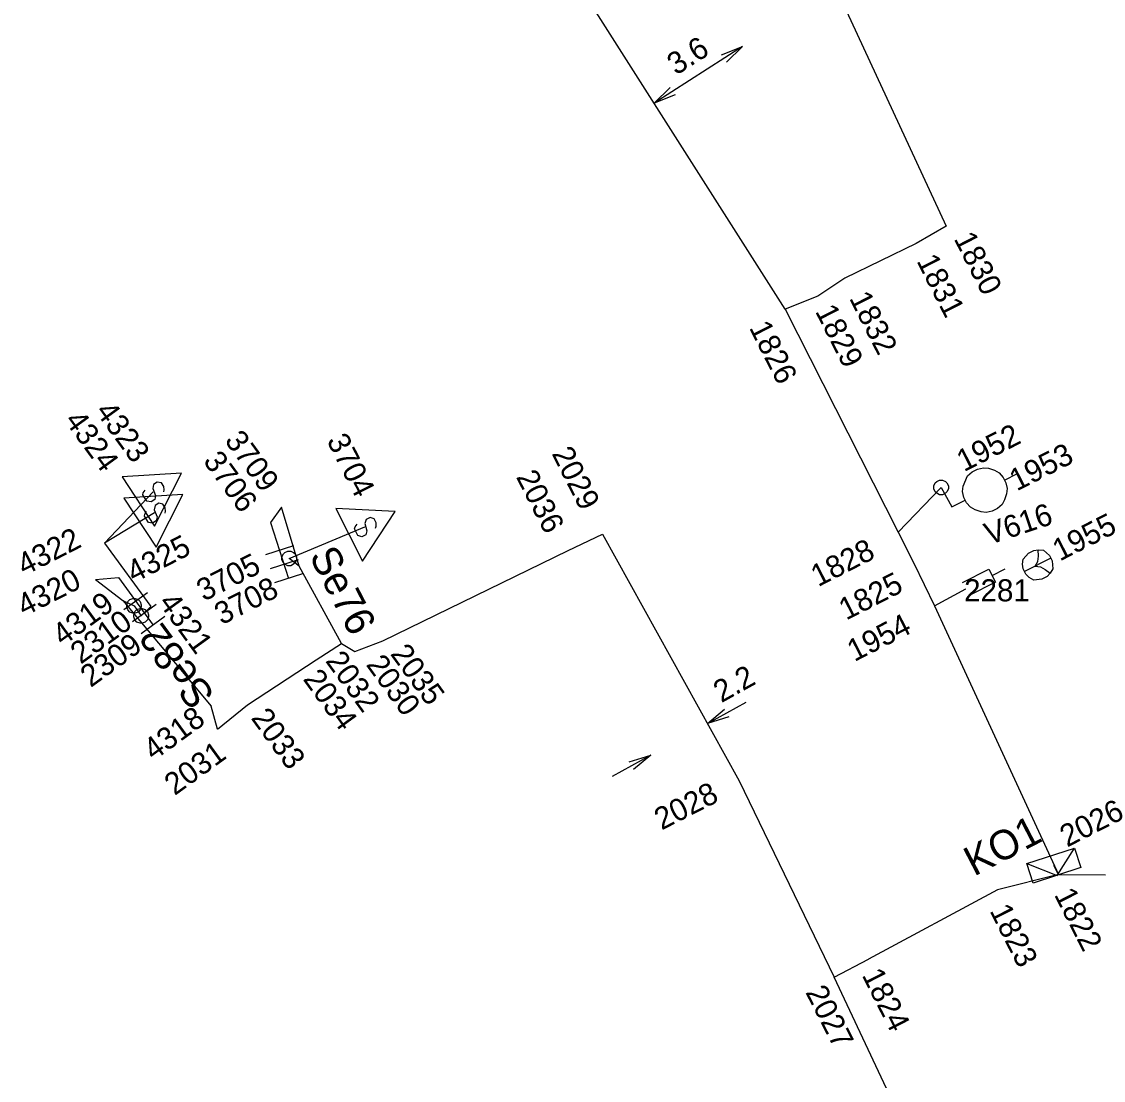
# Model space of a CAD drawing. Extents: x -535557 to -534097, y -1142175 to -1136716.
# Drawn here: x -534476.46 to -534439.74, y -1139633.14 to -1139597.2 of the extents above; entities that cross this region are included whole.
import ezdxf

# ---------------------------------------------------------------- set-up
doc = ezdxf.new("R2010")
doc.units = 0
doc.layers.add('Default', color=7, linetype='Continuous')
doc.layers.add('SS_SZDC', color=7, linetype='Continuous')

# ---------------------------------------------------------------- blocks, each defined once
blk = doc.blocks.new('POINT_DISPLAY')
at = {"layer": 'Default'}
blk.add_line((0, 0), (0, 0), dxfattribs=at)

msp = doc.modelspace()

# ---------------------------------------------------------------- linework, layer by layer
at = {"layer": 'SS_SZDC'}
for p, q in [((-534451.939, -1139589.35), (-534445.079, -1139604.139)), ((-534450.539, -1139606.959), (-534458.239, -1139594.87)), ((-534451.987, -1139598.045), (-534454.996, -1139599.962)), ((-534452.7, -1139598.322), (-534451.987, -1139598.045)), ((-534451.987, -1139598.045), (-534452.539, -1139598.575)), ((-534454.996, -1139599.962), (-534454.444, -1139599.433)), ((-534454.283, -1139599.686), (-534454.996, -1139599.962)), ((-534445.079, -1139604.139), (-534446.1, -1139604.729)), ((-534446.1, -1139604.729), (-534448.52, -1139605.909)), ((-534448.52, -1139605.909), (-534449.43, -1139606.52)), ((-534449.43, -1139606.52), (-534450.539, -1139606.959)), ((-534450.539, -1139606.959), (-534446.71, -1139614.53)), ((-534471.038, -1139612.528), (-534473.05, -1139612.653)), ((-534471.952, -1139614.325), (-534471.038, -1139612.528)), ((-534444.351, -1139612.615), (-534444.195, -1139612.479)), ((-534444.195, -1139612.479), (-534444.017, -1139612.388)), ((-534444.017, -1139612.388), (-534443.816, -1139612.342)), ((-534443.816, -1139612.342), (-534443.637, -1139612.363)), ((-534443.637, -1139612.363), (-534443.435, -1139612.429)), ((-534443.435, -1139612.429), (-534443.278, -1139612.517)), ((-534443.278, -1139612.517), (-534443.143, -1139612.672)), ((-534443.097, -1139612.762), (-534442.652, -1139612.535)), ((-534473.05, -1139612.653), (-534471.952, -1139614.325)), ((-534471.984, -1139612.91), (-534472.013, -1139613.048)), ((-534471.859, -1139612.828), (-534471.984, -1139612.91)), ((-534471.72, -1139612.856), (-534471.859, -1139612.828)), ((-534471.638, -1139612.982), (-534471.72, -1139612.856)), ((-534445.5, -1139612.96), (-534445.449, -1139612.86)), ((-534445.449, -1139612.86), (-534445.4, -1139612.81)), ((-534445.4, -1139612.81), (-534445.3, -1139612.76)), ((-534445.3, -1139612.76), (-534445.199, -1139612.76)), ((-534445.199, -1139612.76), (-534445.099, -1139612.81)), ((-534445.099, -1139612.81), (-534445.05, -1139612.86)), ((-534445.05, -1139612.86), (-534445, -1139612.96)), ((-534444.505, -1139612.973), (-534444.351, -1139612.615)), ((-534443.143, -1139612.672), (-534443.052, -1139612.851)), ((-534443.052, -1139612.851), (-534443.006, -1139613.052)), ((-534473.649, -1139614.899), (-534472, -1139613.159)), ((-534470.988, -1139613.248), (-534473, -1139613.373)), ((-534472.347, -1139613.268), (-534472.333, -1139613.199)), ((-534472.21, -1139613.477), (-534472.347, -1139613.268)), ((-534472.333, -1139613.199), (-534472.276, -1139613.102)), ((-534472.013, -1139613.048), (-534471.917, -1139613.285)), ((-534471.917, -1139613.285), (-534471.946, -1139613.423)), ((-534471.902, -1139615.045), (-534470.988, -1139613.248)), ((-534471.639, -1139613.162), (-534471.625, -1139613.093)), ((-534471.625, -1139613.093), (-534471.638, -1139612.982)), ((-534446.71, -1139614.53), (-534445.25, -1139613.01)), ((-534445.5, -1139613.06), (-534445.5, -1139612.96)), ((-534445.449, -1139613.16), (-534445.5, -1139613.06)), ((-534445.4, -1139613.21), (-534445.449, -1139613.16)), ((-534445.3, -1139613.26), (-534445.4, -1139613.21)), ((-534445.199, -1139613.26), (-534445.3, -1139613.26)), ((-534445.25, -1139613.01), (-534444.88, -1139613.67)), ((-534445.099, -1139613.21), (-534445.199, -1139613.26)), ((-534445.05, -1139613.16), (-534445.099, -1139613.21)), ((-534445, -1139613.06), (-534445.05, -1139613.16)), ((-534445, -1139612.96), (-534445, -1139613.06)), ((-534444.526, -1139613.153), (-534444.505, -1139612.973)), ((-534444.479, -1139613.353), (-534444.526, -1139613.153)), ((-534443.027, -1139613.231), (-534443.092, -1139613.432)), ((-534443.006, -1139613.052), (-534443.027, -1139613.231)), ((-534473, -1139613.373), (-534471.902, -1139615.045)), ((-534472.071, -1139613.506), (-534472.21, -1139613.477)), ((-534471.946, -1139613.423), (-534472.071, -1139613.506)), ((-534471.934, -1139613.63), (-534471.963, -1139613.768)), ((-534471.809, -1139613.548), (-534471.934, -1139613.63)), ((-534471.67, -1139613.576), (-534471.809, -1139613.548)), ((-534471.588, -1139613.702), (-534471.67, -1139613.576)), ((-534467.64, -1139613.68), (-534468.02, -1139614.2)), ((-534467.039, -1139615.69), (-534467.64, -1139613.68)), ((-534444.88, -1139613.67), (-534444.434, -1139613.443)), ((-534444.434, -1139613.443), (-534444.479, -1139613.353)), ((-534444.389, -1139613.532), (-534444.434, -1139613.443)), ((-534444.253, -1139613.687), (-534444.389, -1139613.532)), ((-534444.096, -1139613.775), (-534444.253, -1139613.687)), ((-534443.181, -1139613.59), (-534443.336, -1139613.725)), ((-534443.092, -1139613.432), (-534443.181, -1139613.59)), ((-534471.949, -1139613.879), (-534473.649, -1139614.899)), ((-534472.297, -1139613.988), (-534472.283, -1139613.919)), ((-534472.16, -1139614.197), (-534472.297, -1139613.988)), ((-534472.283, -1139613.919), (-534472.226, -1139613.822)), ((-534471.963, -1139613.768), (-534471.867, -1139614.005)), ((-534471.867, -1139614.005), (-534471.896, -1139614.143)), ((-534471.589, -1139613.882), (-534471.575, -1139613.813)), ((-534471.575, -1139613.813), (-534471.588, -1139613.702)), ((-534465.798, -1139613.731), (-534464.89, -1139615.513)), ((-534463.785, -1139613.827), (-534465.798, -1139613.731)), ((-534464.89, -1139615.513), (-534463.785, -1139613.827)), ((-534464.633, -1139614.035), (-534464.767, -1139614.103)), ((-534464.498, -1139614.079), (-534464.633, -1139614.035)), ((-534443.894, -1139613.841), (-534444.096, -1139613.775)), ((-534443.715, -1139613.862), (-534443.894, -1139613.841)), ((-534443.514, -1139613.816), (-534443.715, -1139613.862)), ((-534443.336, -1139613.725), (-534443.514, -1139613.816)), ((-534472.021, -1139614.226), (-534472.16, -1139614.197)), ((-534471.896, -1139614.143), (-534472.021, -1139614.226)), ((-534468.02, -1139614.2), (-534467.401, -1139616.102)), ((-534467.38, -1139615.42), (-534464.81, -1139614.35)), ((-534465.167, -1139614.419), (-534465.145, -1139614.352)), ((-534465.053, -1139614.642), (-534465.167, -1139614.419)), ((-534465.145, -1139614.352), (-534465.078, -1139614.262)), ((-534464.767, -1139614.103), (-534464.81, -1139614.238)), ((-534464.81, -1139614.238), (-534464.741, -1139614.483)), ((-534464.43, -1139614.212), (-534464.498, -1139614.079)), ((-534464.451, -1139614.392), (-534464.43, -1139614.324)), ((-534464.43, -1139614.324), (-534464.43, -1139614.212)), ((-534464.919, -1139614.686), (-534465.053, -1139614.642)), ((-534464.785, -1139614.618), (-534464.919, -1139614.686)), ((-534464.741, -1139614.483), (-534464.785, -1139614.618)), ((-534457.909, -1139615.149), (-534456.75, -1139614.6)), ((-534456.75, -1139614.6), (-534452.109, -1139622.969)), ((-534446.71, -1139614.53), (-534446.17, -1139615.579)), ((-534473.649, -1139614.899), (-534472.079, -1139617.049)), ((-534467.235, -1139614.996), (-534468.186, -1139615.305)), ((-534464.199, -1139618.219), (-534457.909, -1139615.149)), ((-534442.286, -1139615.239), (-534442.107, -1139615.149)), ((-534442.107, -1139615.149), (-534441.951, -1139615.125)), ((-534441.951, -1139615.125), (-534441.772, -1139615.146)), ((-534441.949, -1139615.349), (-534441.951, -1139615.125)), ((-534441.772, -1139615.146), (-534441.569, -1139615.323)), ((-534467.08, -1139615.472), (-534468.032, -1139615.781)), ((-534467.63, -1139615.37), (-534467.58, -1139615.27)), ((-534467.63, -1139615.47), (-534467.63, -1139615.37)), ((-534467.58, -1139615.57), (-534467.63, -1139615.47)), ((-534467.58, -1139615.27), (-534467.53, -1139615.22)), ((-534467.53, -1139615.22), (-534467.43, -1139615.17)), ((-534467.43, -1139615.17), (-534467.33, -1139615.17)), ((-534467.039, -1139615.69), (-534467.38, -1139615.42)), ((-534467.33, -1139615.17), (-534467.23, -1139615.22)), ((-534467.23, -1139615.22), (-534467.18, -1139615.27)), ((-534467.18, -1139615.27), (-534467.13, -1139615.37)), ((-534467.13, -1139615.47), (-534467.18, -1139615.57)), ((-534467.13, -1139615.37), (-534467.13, -1139615.47)), ((-534442.484, -1139615.621), (-534442.463, -1139615.442)), ((-534442.463, -1139615.442), (-534442.286, -1139615.239)), ((-534441.524, -1139615.413), (-534442.415, -1139615.866)), ((-534442.059, -1139615.685), (-534441.97, -1139615.528)), ((-534441.97, -1139615.528), (-534441.949, -1139615.349)), ((-534441.569, -1139615.323), (-534441.479, -1139615.502)), ((-534441.479, -1139615.502), (-534441.454, -1139615.77)), ((-534467.53, -1139615.62), (-534467.58, -1139615.57)), ((-534467.43, -1139615.67), (-534467.53, -1139615.62)), ((-534467.33, -1139615.67), (-534467.43, -1139615.67)), ((-534467.23, -1139615.62), (-534467.33, -1139615.67)), ((-534467.18, -1139615.57), (-534467.23, -1139615.62)), ((-534465.6, -1139618.309), (-534467.039, -1139615.69)), ((-534446.17, -1139615.579), (-534445.469, -1139617.03)), ((-534444.523, -1139616.237), (-534443.632, -1139615.783)), ((-534443.632, -1139615.783), (-534443.405, -1139616.228)), ((-534443.518, -1139616.006), (-534443.073, -1139615.779)), ((-534442.46, -1139615.777), (-534442.484, -1139615.621)), ((-534442.37, -1139615.956), (-534442.46, -1139615.777)), ((-534442.059, -1139615.685), (-534441.88, -1139615.706)), ((-534441.88, -1139615.706), (-534441.722, -1139615.794)), ((-534441.722, -1139615.794), (-534441.542, -1139615.927)), ((-534441.454, -1139615.77), (-534441.542, -1139615.927)), ((-534473.96, -1139616.139), (-534473.18, -1139616.069)), ((-534473.96, -1139616.139), (-534473.029, -1139616.85)), ((-534473.18, -1139616.069), (-534472.004, -1139617.688)), ((-534466.926, -1139615.947), (-534467.877, -1139616.256)), ((-534443.405, -1139616.228), (-534444.296, -1139616.682)), ((-534442.257, -1139616.067), (-534442.37, -1139615.956)), ((-534442.1, -1139616.155), (-534442.257, -1139616.067)), ((-534441.832, -1139616.13), (-534442.1, -1139616.155)), ((-534441.653, -1139616.04), (-534441.832, -1139616.13)), ((-534441.542, -1139615.927), (-534441.653, -1139616.04)), ((-534472.187, -1139616.585), (-534472.996, -1139617.172)), ((-534445.469, -1139617.03), (-534444.409, -1139616.459)), ((-534473.029, -1139616.85), (-534470.029, -1139620.44)), ((-534473.029, -1139616.85), (-534472.649, -1139617.03)), ((-534472.897, -1139616.994), (-534472.862, -1139616.888)), ((-534472.897, -1139617.065), (-534472.897, -1139616.994)), ((-534472.862, -1139616.888), (-534472.791, -1139616.817)), ((-534472.791, -1139616.817), (-534472.685, -1139616.782)), ((-534471.893, -1139616.989), (-534472.702, -1139617.577)), ((-534472.685, -1139616.782), (-534472.614, -1139616.782)), ((-534472.614, -1139616.782), (-534472.508, -1139616.817)), ((-534472.508, -1139616.817), (-534472.437, -1139616.888)), ((-534472.437, -1139616.888), (-534472.402, -1139616.994)), ((-534472.402, -1139616.994), (-534472.402, -1139617.065)), ((-534472.862, -1139617.171), (-534472.897, -1139617.065)), ((-534472.791, -1139617.242), (-534472.862, -1139617.171)), ((-534472.685, -1139617.277), (-534472.791, -1139617.242)), ((-534472.614, -1139617.277), (-534472.685, -1139617.277)), ((-534472.657, -1139617.334), (-534472.622, -1139617.228)), ((-534472.657, -1139617.405), (-534472.657, -1139617.334)), ((-534472.649, -1139617.03), (-534472.409, -1139617.37)), ((-534472.622, -1139617.228), (-534472.551, -1139617.157)), ((-534472.508, -1139617.242), (-534472.614, -1139617.277)), ((-534472.551, -1139617.157), (-534472.445, -1139617.122)), ((-534472.437, -1139617.171), (-534472.508, -1139617.242)), ((-534472.445, -1139617.122), (-534472.374, -1139617.122)), ((-534472.402, -1139617.065), (-534472.437, -1139617.171)), ((-534472.079, -1139617.049), (-534472.409, -1139617.37)), ((-534472.374, -1139617.122), (-534472.268, -1139617.157)), ((-534472.268, -1139617.157), (-534472.197, -1139617.228)), ((-534472.197, -1139617.228), (-534472.162, -1139617.334)), ((-534472.162, -1139617.334), (-534472.162, -1139617.405)), ((-534445.469, -1139617.03), (-534441.26, -1139626.149)), ((-534472.622, -1139617.511), (-534472.657, -1139617.405)), ((-534472.551, -1139617.582), (-534472.622, -1139617.511)), ((-534472.445, -1139617.617), (-534472.551, -1139617.582)), ((-534472.374, -1139617.617), (-534472.445, -1139617.617)), ((-534471.599, -1139617.394), (-534472.408, -1139617.981)), ((-534472.268, -1139617.582), (-534472.374, -1139617.617)), ((-534472.197, -1139617.511), (-534472.268, -1139617.582)), ((-534472.162, -1139617.405), (-534472.197, -1139617.511)), ((-534466.46, -1139618.86), (-534465.6, -1139618.309)), ((-534465.6, -1139618.309), (-534465.149, -1139618.579)), ((-534465.149, -1139618.579), (-534464.199, -1139618.219)), ((-534468.8, -1139620.389), (-534466.46, -1139618.86)), ((-534453.185, -1139621.03), (-534451.873, -1139620.302)), ((-534469.819, -1139621.219), (-534470.029, -1139620.44)), ((-534469.819, -1139621.219), (-534468.8, -1139620.389)), ((-534453.185, -1139621.03), (-534452.602, -1139620.535)), ((-534452.456, -1139620.797), (-534453.185, -1139621.03)), ((-534455.108, -1139622.096), (-534456.419, -1139622.823)), ((-534455.836, -1139622.328), (-534455.108, -1139622.096)), ((-534455.108, -1139622.096), (-534455.691, -1139622.59)), ((-534452.109, -1139622.969), (-534448.88, -1139629.639)), ((-534442.336, -1139625.779), (-534440.719, -1139625.254)), ((-534441.311, -1139626.182), (-534440.719, -1139625.254)), ((-534440.719, -1139625.254), (-534440.503, -1139625.92)), ((-534442.12, -1139626.445), (-534442.336, -1139625.779)), ((-534442.336, -1139625.779), (-534441.311, -1139626.182)), ((-534441.26, -1139626.149), (-534443.34, -1139626.67)), ((-534440.503, -1139625.92), (-534442.12, -1139626.445)), ((-534441.26, -1139626.149), (-534441.42, -1139625.85)), ((-534441.26, -1139626.149), (-534439.67, -1139626.159)), ((-534443.34, -1139626.67), (-534447.71, -1139629.03)), ((-534448.88, -1139629.639), (-534447.71, -1139629.03)), ((-534443.079, -1139641.94), (-534448.88, -1139629.639))]:
    msp.add_line(p, q, dxfattribs=at)

# ---------------------------------------------------------------- block references
for p in [(-534445.079, -1139604.139), (-534446.1, -1139604.729), (-534448.52, -1139605.909), (-534449.43, -1139606.52), (-534450.539, -1139606.959), (-534472, -1139613.159), (-534445.25, -1139613.01), (-534445.25, -1139613.01), (-534467.64, -1139613.68), (-534444.88, -1139613.67), (-534471.949, -1139613.879), (-534468.02, -1139614.2), (-534464.81, -1139614.35), (-534456.75, -1139614.6), (-534446.71, -1139614.53), (-534473.649, -1139614.899), (-534457.909, -1139615.149), (-534467.38, -1139615.42), (-534467.38, -1139615.42), (-534467.039, -1139615.69), (-534446.17, -1139615.579), (-534441.97, -1139615.639), (-534473.96, -1139616.139), (-534473.18, -1139616.069), (-534444.409, -1139616.459), (-534473.029, -1139616.85), (-534472.649, -1139617.03), (-534472.649, -1139617.03), (-534472.079, -1139617.049), (-534445.469, -1139617.03), (-534472.409, -1139617.37), (-534472.409, -1139617.37), (-534465.6, -1139618.309), (-534464.199, -1139618.219), (-534465.149, -1139618.579), (-534466.46, -1139618.86), (-534470.029, -1139620.44), (-534468.8, -1139620.389), (-534469.819, -1139621.219), (-534452.109, -1139622.969), (-534441.42, -1139625.85), (-534441.26, -1139626.149), (-534443.34, -1139626.67), (-534447.71, -1139629.03), (-534448.88, -1139629.639)]:
    msp.add_blockref('POINT_DISPLAY', p, dxfattribs=at)

# ---------------------------------------------------------------- texts
for s, height, rotation, p in [('3.6', 0.75, 32.4927, (-534454.243, -1139599.037)), ('1830', 0.75, 297, (-534444.83, -1139604.564)), ('1831', 0.75, 297, (-534446.096, -1139605.319)), ('1832', 0.75, 297, (-534448.383, -1139606.585)), ('1829', 0.75, 297, (-534449.538, -1139607.029)), ('1826', 0.75, 297, (-534451.781, -1139607.585)), ('4323', 0.75, 306, (-534473.984, -1139610.432)), ('4324', 0.75, 306, (-534475.032, -1139610.742)), ('3709', 0.75, 306, (-534469.597, -1139611.422)), ('1952', 0.75, 27, (-534444.475, -1139612.497)), ('3704', 0.75, 297, (-534466.122, -1139611.419)), ('3706', 0.75, 306, (-534470.326, -1139612.12)), ('2029', 0.75, 297, (-534458.482, -1139611.859)), ('1953', 0.75, 27, (-534442.682, -1139613.151)), ('2036', 0.75, 297, (-534459.691, -1139612.651)), ('V616', 0.75, 18.3757, (-534443.627, -1139614.974)), ('1955', 0.75, 27, (-534441.222, -1139615.53)), ('4322', 0.75, 27, (-534476.371, -1139616.021)), ('4325', 0.75, 27, (-534472.651, -1139616.267)), ('1828', 0.75, 27, (-534449.427, -1139616.401)), ('Se76', 1, 297.3757, (-534466.717, -1139615.338)), ('3705', 0.75, 27, (-534470.278, -1139616.893)), ('4320', 0.75, 27, (-534476.374, -1139617.406)), ('1825', 0.75, 27, (-534448.472, -1139617.534)), ('3708', 0.75, 27, (-534469.672, -1139617.695)), ('4319', 0.75, 36, (-534475.073, -1139618.419)), ('4321', 0.75, 306, (-534471.843, -1139616.923)), ('2310', 0.75, 36, (-534474.458, -1139619.033)), ('1954', 0.75, 27, (-534448.192, -1139618.941)), ('Se82', 1, 126.3757, (-534469.876, -1139620.051)), ('2309', 0.75, 36, (-534474.12, -1139619.823)), ('2035', 0.75, 306, (-534463.97, -1139618.666)), ('2032', 0.75, 306, (-534466.173, -1139618.904)), ('2030', 0.75, 306, (-534464.794, -1139619.031)), ('2034', 0.75, 306, (-534466.934, -1139619.522)), ('2.2', 0.75, 29.0023, (-534452.711, -1139620.338)), ('4318', 0.75, 36, (-534471.983, -1139622.312)), ('2033', 0.75, 306, (-534468.7, -1139620.843)), ('2031', 0.75, 36, (-534471.268, -1139623.491)), ('2028', 0.75, 27, (-534454.738, -1139624.66)), ('2026', 0.75, 27, (-534440.972, -1139625.24)), ('KO1', 1, 27.3757, (-534444.133, -1139626.228)), ('1822', 0.75, 297, (-534441.425, -1139626.835)), ('1823', 0.75, 297, (-534443.615, -1139627.383)), ('1824', 0.75, 297, (-534447.955, -1139629.566)), ('2027', 0.75, 297, (-534449.867, -1139630.147))]:
    msp.add_text(s, height=height, rotation=rotation, dxfattribs=at).set_placement(p)
msp.add_text('2281', height=0.75, dxfattribs=at).set_placement((-534444.469, -1139616.88))

doc.saveas('drawing.dxf')
